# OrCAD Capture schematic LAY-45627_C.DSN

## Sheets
1 PAGE2: size A4; title: Audio / sensors expansion board; rev: 1; note: PCB2460-1
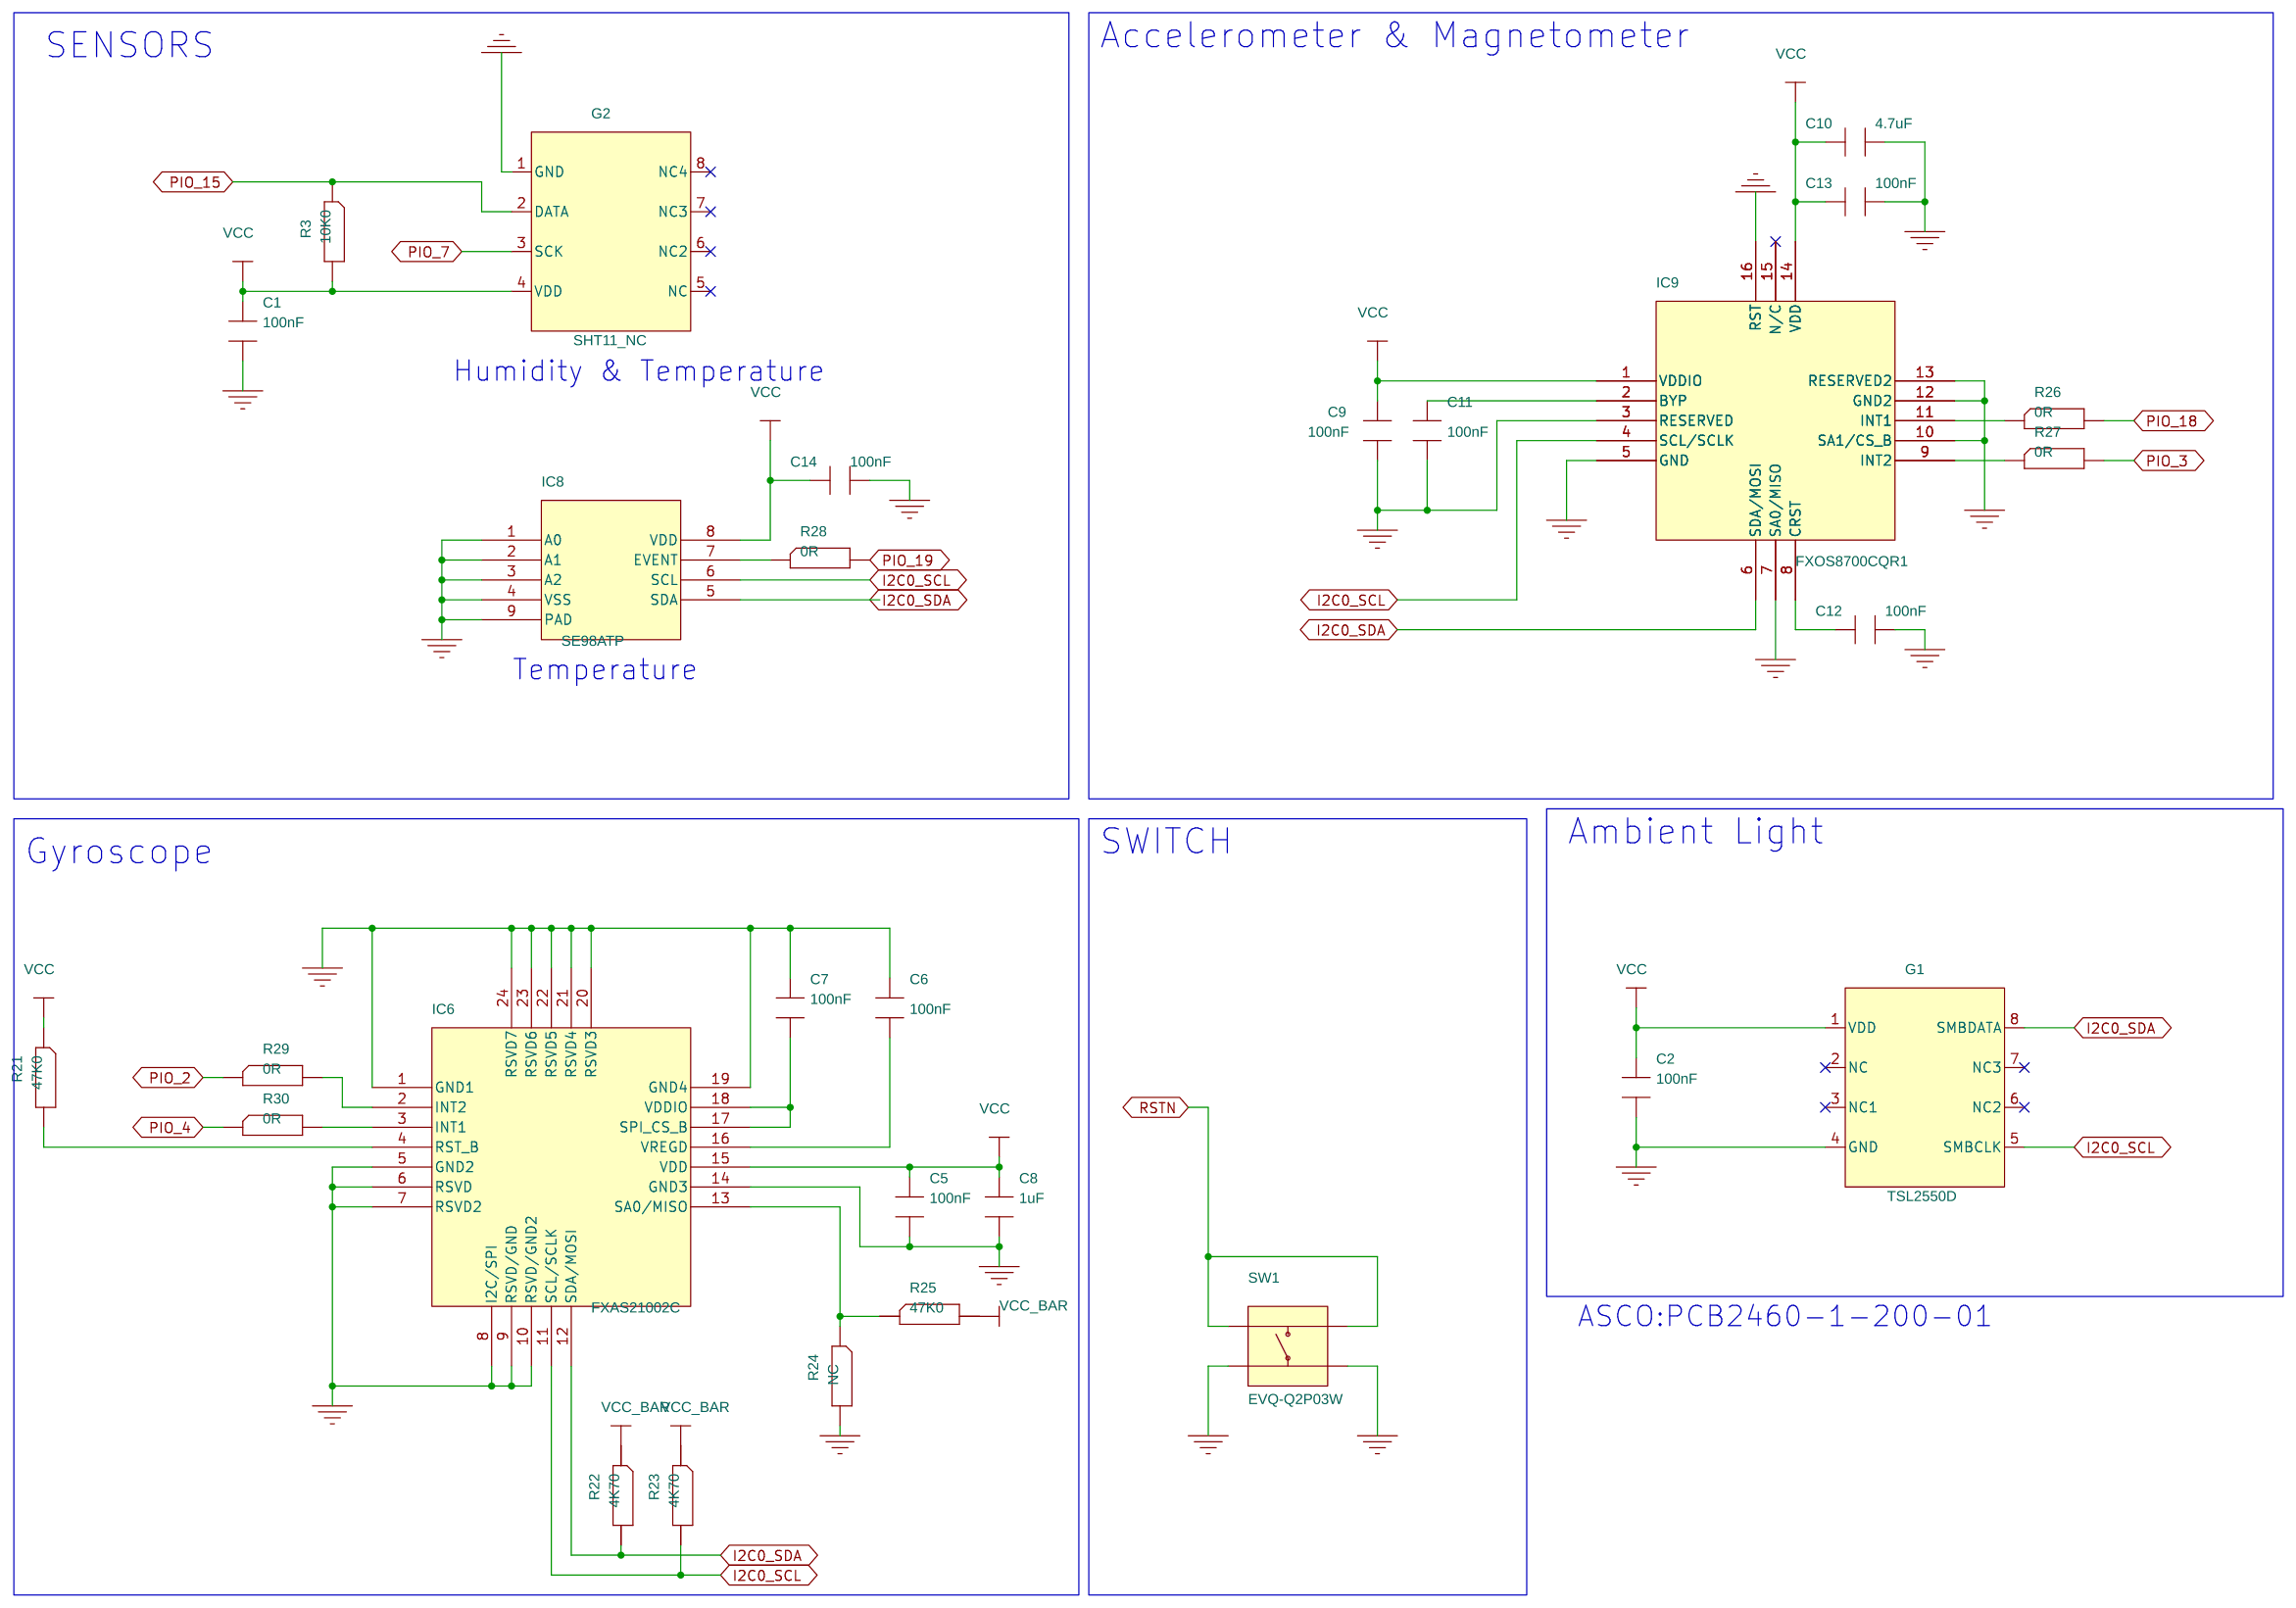
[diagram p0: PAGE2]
2 PAGE1: size A4
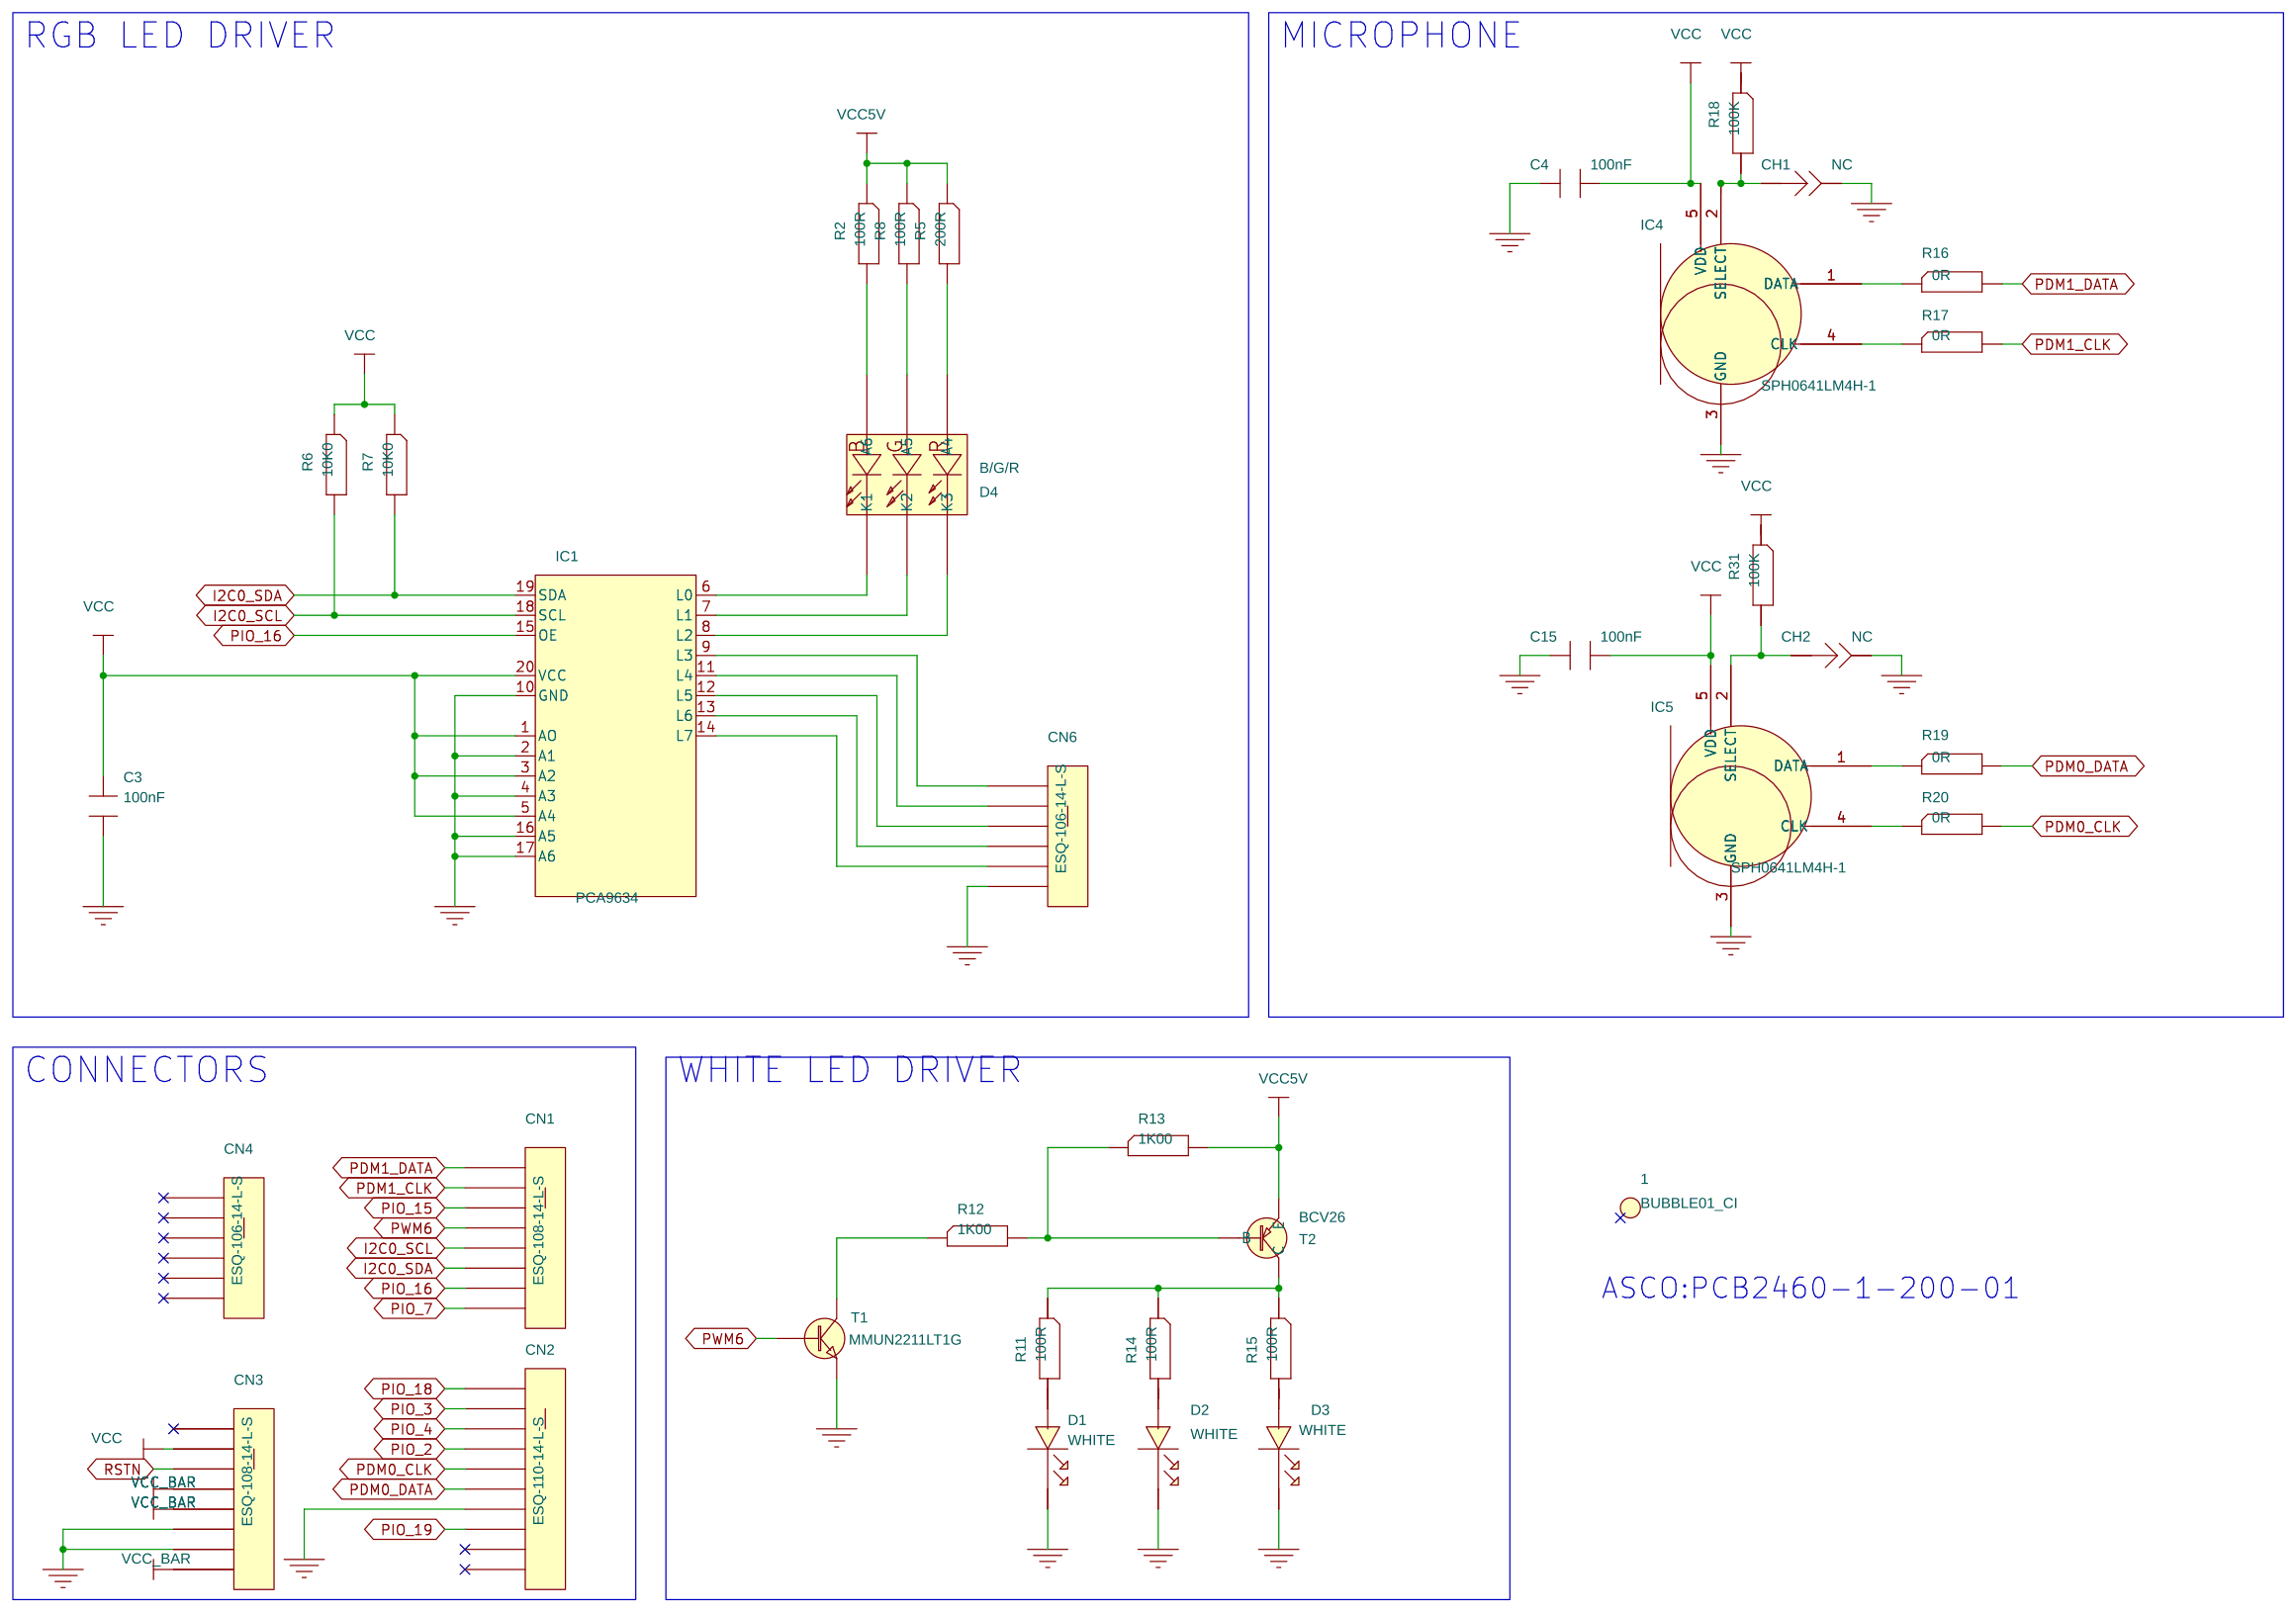
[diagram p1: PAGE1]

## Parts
sheet PAGE1
1  BUBBLE01_CI  [BUBBLE_DIAM8]
C3  100nF  [C0603]
C4  100nF  [C0603]
C15  100nF  [C0603]
CH1  NC  [CHEVRON_0603_O]
CH2  NC  [CHEVRON_0603_O]
CN1  ESQ-108-14-L-S  [ESQ-108-14-L-S]
CN2  ESQ-110-14-L-S  [ESQ-110-14-L-S]
CN3  ESQ-108-14-L-S  [ESQ-108-14-L-S]
CN4  ESQ-106-14-L-S  [ESQ-106-14-L-S]
CN6  ESQ-106-14-L-S  [ESQ-106-14-L-S]
D1  WHITE  [LED_D5_A_K]
D2  WHITE  [LED_D5_A_K]
D3  WHITE  [LED_D5_A_K]
D4  B/G/R  [LED_PLCC6]
IC1  PCA9634  [TSSOP20_175_065]
IC4  SPH0641LM4H-1  [SPH0641LM4H-1]
IC5  SPH0641LM4H-1  [SPH0641LM4H-1]
R2  100R  [R0603]
R5  200R  [R0603]
R6  10K0  [R0603]
R7  10K0  [R0603]
R8  100R  [R0603]
R11  100R  [R0603]
R12  1K00  [R0603]
R13  1K00  [R0603]
R14  100R  [R0603]
R15  100R  [R0603]
R16  0R  [R0603]
R17  0R  [R0603]
R18  100K  [R0603]
R19  0R  [R0603]
R20  0R  [R0603]
R31  100K  [R0603]
T1  MMUN2211LT1G  [SOT23]
T2  BCV26  [SOT23]
sheet PAGE2
C1  100nF  [C0603]
C2  100nF  [C0603]
C5  100nF  [C0603]
C6  100nF  [C0603]
C7  100nF  [C0603]
C8  1uF  [C0603]
C9  100nF  [C0603]
C10  4.7uF  [C0603]
C11  100nF  [C0603]
C12  100nF  [C0603]
C13  100nF  [C0603]
C14  100nF  [C0603]
G1  TSL2550D  [SOIC8]
G2  SHT11_NC  [Sensor_SHT11]
IC6  FXAS21002C  [QFN24_050_4x4]
IC8  SE98ATP  [sot1069-2_hwson8]
IC9  FXOS8700CQR1  [QFN16_050_sq3_nopad]
R3  10K0  [R0603]
R21  47K0  [R0603]
R22  4K70  [R0603]
R23  4K70  [R0603]
R24  NC  [R0603]
R25  47K0  [R0603]
R26  0R  [R0603]
R27  0R  [R0603]
R28  0R  [R0603]
R29  0R  [R0603]
R30  0R  [R0603]
SW1  EVQ-Q2P03W  [BP_EVQQ2]

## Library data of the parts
1 = BUBBLE: Designation: Printed Circuit Board : OM15081-1 (NXP : Audio / sensors expansion board); Manufacturer_reference: PCB2460-1; Part Number: 0-CI-001068; Part Type: BUBBLE_CI; Supplier: ASCO
C1-C3 = CAPA: Designation: Capacitor 0603 100nF 10% 16V X7R (-55°C+125°C); Gamme: X7R; MANUFACTURER_REFERENCE: YAGEO (PHYCOMP) (CC0603KRX7R7BB104); Package: 603; Part Number: 0-00-300220F; Supplier: FARNELL; Temp: (-55°C+125°C); Tension: 16V; Tol: 10%
C4-C7 C9 C11-C15 = CAPA: Designation: Capacitor 0603 100nF 10% 16V X7R (-55°C+125°C); Gamme: X7R; MANUFACTURER_REFERENCE: AVX (0603YC104KAT2A), KEMET (C0603C104K4RAC), KEMET (C0603C104K4RACTU), MULTICOMP (MC0603B104M160CT), MURATA (GRM188R71C104KA01D), SYFER TECHNOLOGY (0603J0160104KXT), SYFER TECHNOLOGY (0603J016 0104KX@), VISHAY (VJ0603Y104KXJA), VISHAY (VJ0603Y104KXJA@),; Package: 603; Part Number: 0-00-300220; Supplier: RADIOSPARES; Temp: (-55°C+125°C); Tension: 16V; Tol: 10%
CH1 CH2 = CHEVRON_0603_OPEN: Designation: !!! Not Connected !!! (Open By Default); Package: 603; Part Number: 0-00-3CHEVRON-NC; Part Type: CHEVRON
CN1 CN3 = HEADER_8P: Designation: SOCKET, 1ROW, 8WAY Vertical ESQ-108-14-L-S; Manufacturer_reference: SAMTEC (ESQ-108-14-L-S); Package: ESQ; Part Number: 0-00-203814; Part Type: CONNECTOR
CN2 = HEADER_10P: Designation: SOCKET, 1ROW, 10WAY Vertical ESQ-110-14-L-S; Manufacturer_reference: SAMTEC (ESQ-110-14-L-S); Package: ESQ; Part Number: 0-00-204059; Part Type: CONNECTOR
CN4 CN6 = HEADER_6P: Designation: SOCKET, 1ROW, 6WAY Vertical ESQ-106-14-L-S; Manufacturer_reference: SAMTEC (ESQ-106-14-L-S); Package: ESQ; Part Number: 0-00-203813; Part Type: CONNECTOR
D1-D3 = LED: Designation: WHITE LED Diam.5MM (Thru); Manufacturer_reference: MARL (NSPL510DS), MULTICOMP (MCL053SWC-YH1); Package: 5MM; Part Number: 0-00-002137; Temp: (-40°C to 85°C)
D4 = LED_3_PLCC6: Designation: LED SMD PLCC-6 BLUE / GREEN / RED (PLCC-6); Manufacturer_reference: AVAGO TECHNOLOGIES (ASMT-YTB2-0BB02); Package: PLCC-6; Part Number: 0-00-002056; Part Type: LED
IC1 = PCA9634_TSSOP20: Designation: Integrated Circuit PCA9634PW (TSSOP-20); Manufacturer_reference: NXP (PCA9634PW); Package: TSSOP-20; Part Number: 0-00-403825; Part Type: IC
IC4 IC5 = SPH0641LM4H-1: Designation: Integrated Circuit  Microphone; Manufacturer_reference: KNOWLES ACOUSTICS (SPH0641LM4H-1); Package: SMD; Part Number: 0-00-403999; Part Type: IC
R2 R8 R11 R14 R15 = RES: Designation: Resistor 0603 100R 1% 100ppm -; MANUFACTURER_REFERENCE: BOURNS (CR0603-FX-1000ELF), KOA SPEER (RK73H1JTTD1000F), MULTICOMP (MC0063W06031100R), MULTICOMP (MCHP03W8F1000T5E), MULTICOMP (MC 0.063W 0603 1% 100R), SAMSUNG (RC1608F1000@ 0,1W), TT Electronics (CR0603F-100RF), TT Electronics (WCR0603 100R F @), VISHAY; PACKAGE: 603; PPM: 100ppm; Part Number: 0-00-302184; SUPPLIER: FARNELL; TOL: 1%
R5 = RES: Designation: Resistor 0603 200R 1% 100ppm -; MANUFACTURER_REFERENCE: VISHAY (CRCW0603200RFKEA); PACKAGE: 603; PPM: 100ppm; Part Number: 0-00-302371B; SUPPLIER: FARNELL; TOL: 1%
R3 R6 R7 = RES: Designation: Resistor 0603 10K0 1% 100ppm -; MANUFACTURER_REFERENCE: YAGEO (PHYCOMP) (RC0603FR-0710KL); PACKAGE: 603; PPM: 100ppm; Part Number: 0-00-302196D; SUPPLIER: FARNELL; TOL: 1%
R12 R13 = RES: Designation: Resistor 0603 1K00 1% 100ppm -; MANUFACTURER_REFERENCE: BOURNS (CR0603-FX-1001ELF), MULTICOMP (MC0063W060351K), MULTICOMP (MCHP03W8F1001T5E), MULTICOMP (MC 0.063W 0603 5% 1K), TE Connectivity (CRG0603F1K0), TT Electronics (WCR0603-1K0FI), VISHAY (CRCW06031K00FKEA), VISHAY (CRCW06031K00FKEA.), YAGEO (PHYCOMP) (; PACKAGE: 603; PPM: 100ppm; Part Number: 0-00-302318; SUPPLIER: DIGIKEY CORPORATION; TOL: 1%
R16 R17 R19 R20 = RES: Alt_Symbols: 0603R; Designation: Resistor 0603 0R 1% 100ppm -; MANUFACTURER_REFERENCE: KOA SPEER (RK73Z1JTTD); PACKAGE: 603; PPM: 100ppm; Part Number: 0-00-302172A; SUPPLIER: MOUSER ELECTRONICS; TOL: 1%
R18 R31 = RES: Designation: Resistor 0603 100K 1% 100ppm -; MANUFACTURER_REFERENCE: BOURNS (CR0603-FX-1003ELF), BOURNS (CR0805-FX-1003GLF), KOA SPEER (RK73H1JTTD1003F), MULTICOMP (MC0063W06031100K), MULTICOMP (MC 0.063W 0603 1% 100K), VISHAY (RCA0603100KFKEA), VISHAY (CRCW0603100KFKEA), VISHAY (CHPHT0603K1003FGT), YAGEO (PHYCOMP) (232270; PACKAGE: 603; PPM: 100ppm; Part Number: 0-00-302177; SUPPLIER: FARNELL; TOL: 1%
T1 = NPN_B1_E2_C3: Designation: NPN Transistors With Monolithic Bias Ressitor Network MMUN2211LT1G (SOT-23); Manufacturer_reference: ON SEMICONDUCTOR (MMUN2211LT1G); Package: SOT-23; Part Number: 0-00-403883; Part Type: TRANSISTOR_NPN
T2 = PNP_B1_E2_C3: Designation: PNP Darlington Transistor BCV26 (SOT-23); Manufacturer_reference: FAIRCHILD SEMICONDUCTOR (BCV26); Package: SOT-23; Part Number: 0-00-403822; Part Type: TRANSISTOR_PNP
C8 = CAPA: Designation: Capacitor 0603 1uF 10% 10V X5R (-55°C+85°C); Gamme: X5R; MANUFACTURER_REFERENCE: AVX (0603ZD105KAT2A), TDK (C1608X5R1A105K080AC); Package: 603; Part Number: 0-00-300206; Supplier: FARNELL; Temp: (-55°C+85°C); Tension: 10V; Tol: 10%
C10 = CAPA: Designation: Capacitor 0603 4.7uF 10% 10V X5R; Gamme: X5R; MANUFACTURER_REFERENCE: AVX (0603ZD475KAT2A); Package: 603; Part Number: 0-00-300383; Supplier: DIGIKEY CORPORATION; Tension: 10V; Tol: 10%
G1 = SENSOR_TLS2550D: Designation: Light Sensor - TSL2550D; Manufacturer_reference: AMS (TLS2550D), AMS (TSL2550D.); Package: Light; Part Number: 0-00-403823; Part Type: SENSOR
G2 = SENSOR_SHT11: Designation: Humidity Sensor - SHT11 !!! Not Connected !!!; Manufacturer_reference: SENSIRION (SHT11), SENSIRION (SHT11...); Package: Humidity; Part Number: 0-00-403824NC; Part Type: SENSOR
IC6 = FXAS21002C: Designation: Integrated Circuit Gyroscope FXAS21002C (QFN-24); Manufacturer_reference: NXP(FXAS21002C); Package: QFN-24; Part Number: 0-00-404000; Part Type: IC; Temp: (-40°C to +85°C
IC8 = SE98ATP: Designation: Integrated Circuit  DDR memory module temp; Manufacturer_reference: NXP(SE98ATP); Package: SOT1069-2; Part Number: 0-00-4SE98ATP; Part Type: IC
IC9 = FXOS8700CQR1: Designation: Integrated Circuit Accelerometer/magnetometer FXOS8700CQR1 (QFN-16); Manufacturer_reference: NXP(FXOS8700CQR1); Package: QFN-16; Part Number: 0-00-404001; Part Type: IC; Temp: (-40°C to +85°C)
R21 R25 = RES: Designation: Resistor 0603 47K0 5% 200ppm -; MANUFACTURER_REFERENCE: PANASONIC (ERJ3GEYJ473V), PANASONIC (ERJ-3GEYJ473V), VISHAY (CRCW060347K0JNEA), YAGEO (PHYCOMP) (2322 702 65473); PACKAGE: 603; PPM: 200ppm; Part Number: 0-00-302641; SUPPLIER: FARNELL; TOL: 5%
R22 R23 = RES: Designation: Resistor 0603 4K70 5% 200ppm -; MANUFACTURER_REFERENCE: PANASONIC (ERJ3GEYJ472V), PANASONIC (ERJ-3GEYJ472V); PACKAGE: 603; PPM: 200ppm; Part Number: 0-00-302672; SUPPLIER: FARNELL; TOL: 5%
R24 = RES: Designation: !!! NOT CONNECTED !!!; PACKAGE: 603; Part Number: 0-00-3NC_R0603
R26-R30 = RES: Alt_Symbols: 0603R; Designation: Resistor 0603 0R 1% 100ppm -; MANUFACTURER_REFERENCE: KOA SPEER (RK73Z1JTTD), MULTICOMP (MC0063W06030R), MULTICOMP (MC 0.063W 0603 0R), SAMSUNG (RC1608F0R0@ 0,1W), TE Connectivity (CRG0603ZR), TT Electronics (WCR0603 0R005 J @), VISHAY (RCA06030000ZSEA), VISHAY (CRCW06030000Z0EA), VISHAY (CRCW06030000Z0EB),; PACKAGE: 603; PPM: 100ppm; Part Number: 0-00-302172; SUPPLIER: FARNELL; TOL: 1%
SW1 = BP_EVQQ2: Designation: Switch tactile SPST - EVQ-Q2P03W (EVQQ2); Manufacturer_reference: PANASONIC (EVQQ2P03W), PANASONIC (EVQ-Q2P03W); Package: EVQQ2; Part Number: 0-00-001838; Part Type: COMMUTATOR

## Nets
GND: C1.2 C2.2 C3.2 C4.2 C5.2 C6.2 C7.1 C8.2 C9.1 C10.2 C11.1 C12.1 C13.1 C14.1 C15.2 CH1.2 CH2.2 CN2.7 CN3.6 CN3.7 CN6.6 D1.K D2.K D3.K G1.4(GND) G2.1(GND) IC1.2(A1) IC1.4(A3) IC1.10(GND) IC1.16(A5) IC1.17(A6) IC4.3(GND) IC5.3(GND) IC6.1(GND1) IC6.5(GND2) IC6.6(RSVD) IC6.7(RSVD2) IC6.8(I2C/SPI) IC6.9(RSVD/GND) IC6.10(RSVD/GND2) IC6.14(GND3) IC6.19(GND4) IC6.20(RSVD3) IC6.21(RSVD4) IC6.22(RSVD5) IC6.23(RSVD6) IC6.24(RSVD7) IC8.1(A0) IC8.2(A1) IC8.3(A2) IC8.4(VSS) IC8.9(PAD) IC9.3(RESERVED) IC9.5(GND) IC9.7(SA0/MISO) IC9.10(SA1/CS_B) IC9.12(GND2) IC9.13(RESERVED2) IC9.16(RST) R24.2 SW1.A SW1.AP T1.2(E)
VCC: C1.1 C2.1 C3.1 C4.1 C5.1 C8.1 C9.2 C10.1 C13.2 C14.2 C15.1 CN3.2 G1.1(VDD) G2.4(VDD) IC1.1(AO) IC1.3(A2) IC1.5(A4) IC1.20(VCC) IC4.5(VDD) IC5.5(VDD) IC6.15(VDD) IC8.8(VDD) IC9.1(VDDIO) IC9.14(VDD) R3.2 R6.1 R7.1 R18.1 R21.1 R22.1 R23.1 R25.2 R31.1
VCC3.3V: CN3.4
VCC5V: CN3.5 R2.1 R5.1 R8.1 R13.2 T2.2(E)
VIN: CN3.8
I2C0_SCL: CN1.5 G1.5(SMBCLK) IC1.18(SCL) IC6.11(SCL/SCLK) IC8.6(SCL) IC9.4(SCL/SCLK) R6.2 R23.2
I2C0_SDA: CN1.6 G1.8(SMBDATA) IC1.19(SDA) IC6.12(SDA/MOSI) IC8.5(SDA) IC9.6(SDA/MOSI) R7.2 R22.2
PDM0_CLK: CN2.5 R20.2
PDM0_DATA: CN2.6 R19.2
PDM1_CLK: CN1.2 R17.2
PDM1_DATA: CN1.1 R16.2
PIO_2: CN2.4 R29.1
PIO_3: CN2.2 R27.2
PIO_4: CN2.3 R30.1
PIO_7: CN1.8 G2.3(SCK)
PIO_15: CN1.3 G2.2(DATA) R3.1
PIO_16: CN1.7 IC1.15(OE)
PIO_18: CN2.1 R26.2
PIO_19: CN2.8 R28.2
PWM6: CN1.4 T1.1(B)
RSTN: CN3.3 SW1.B SW1.BP
N03174: D1.A R11.2
N03180: D2.A R14.2
N03190: D3.A R15.2
N03428: R11.1 R14.1 R15.1 T2.3(C)
N03542: R12.2 R13.1 T2.1(B)
N03710: R12.1 T1.3(C)
N05589: CN6.5 IC1.14(L7)
N05601: CN6.4 IC1.13(L6)
N05625: CN6.3 IC1.12(L5)
N05637: CN6.2 IC1.11(L4)
N05653: CN6.1 IC1.9(L3)
N05814: D4.3(K3) IC1.8(L2)
N05832: D4.2(K2) IC1.7(L1)
N05850: D4.1(K1) IC1.6(L0)
N06055: D4.6(A6) R2.2
N06079: D4.5(A5) R8.2
N06104: D4.4(A4) R5.2
N25754: IC6.4(RST_B) R21.2
N28193: IC6.13(SA0/MISO) R24.1 R25.1
N29430: C6.1 IC6.16(VREGD)
N29717: C7.2 IC6.17(SPI_CS_B) IC6.18(VDDIO)
N31644: C11.2 IC9.2(BYP)
N33464: C12.2 IC9.8(CRST)
N60487: IC9.11(INT1) R26.1
N60495: IC9.9(INT2) R27.1
N61570: IC8.7(EVENT) R28.1
N62140: IC6.2(INT2) R29.2
N62201: IC6.3(INT1) R30.2
N66287: IC4.1(DATA) R16.1
N66291: IC4.4(CLK) R17.1
N66417: CH1.1 IC4.2(SELECT) R18.2
N66481: IC5.1(DATA) R19.1
N66485: IC5.4(CLK) R20.1
N77953: CH2.1 IC5.2(SELECT) R31.2

Not connected (* = marked no-connect by the designer): 1 1*; CN2 9* 10*; CN3 1*; CN4 1* 2* 3* 4* 5* 6*; G1 2(NC)* 3(NC1)* 6(NC2)* 7(NC3)*; G2 5(NC)* 6(NC2)* 7(NC3)* 8(NC4)*; IC9 15(N/C)*

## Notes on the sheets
sheet 1
- SENSORS
- Accelerometer & Magnetometer
- Humidity & Temperature
- Temperature
- SWITCH
- Ambient Light
- Gyroscope
- ASCO:PCB2460-1-200-01
sheet 2
- RGB LED DRIVER
- MICROPHONE
- CONNECTORS
- WHITE LED DRIVER
- ASCO:PCB2460-1-200-01
